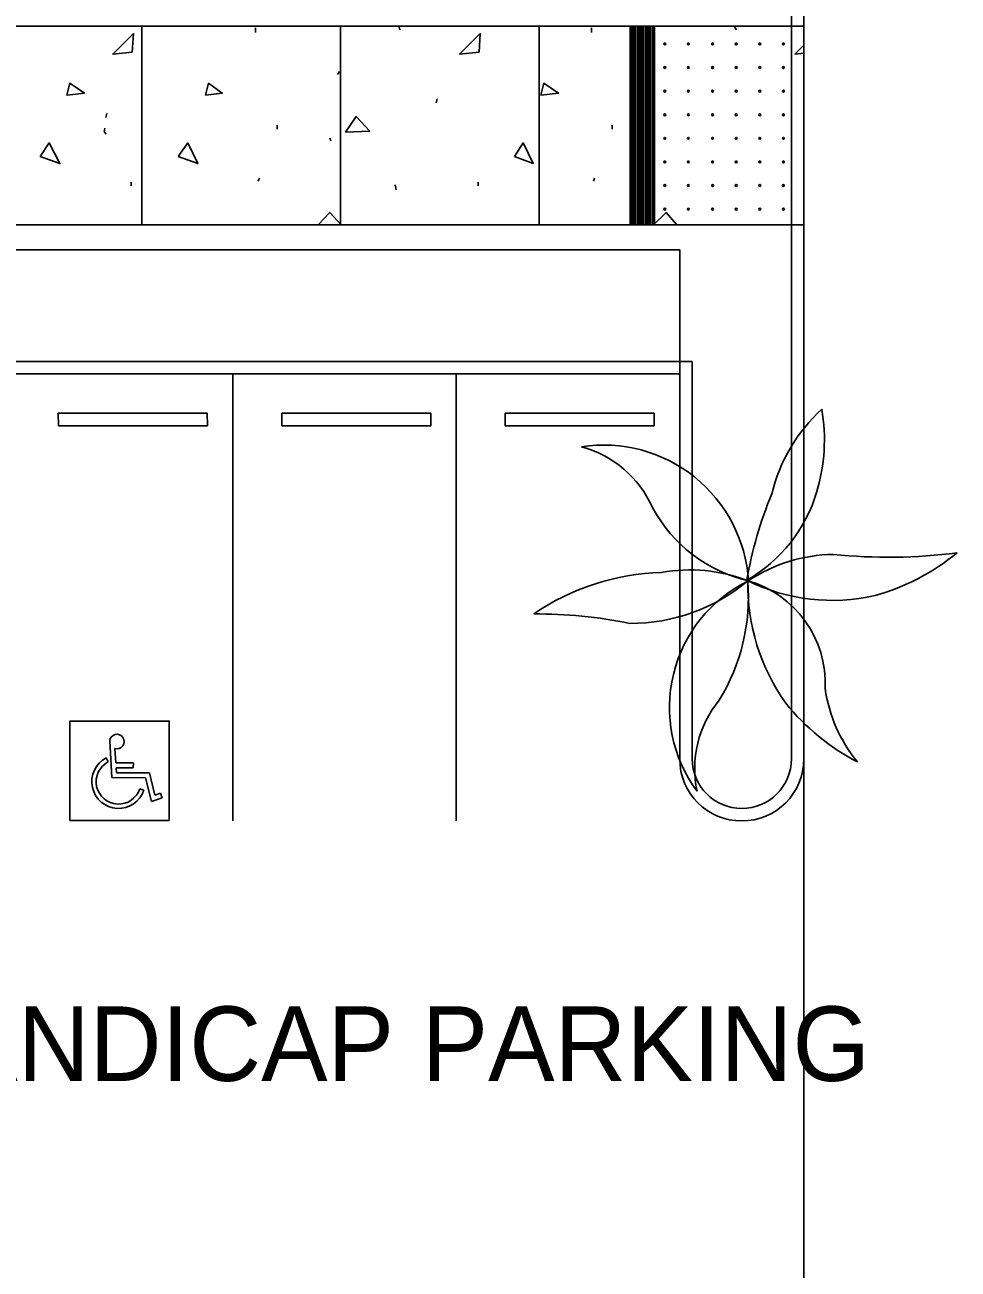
# Model space of a CAD drawing. Extents: x 6712138 to 6712574, y 1869536 to 1870160.
# Drawn here: x 6712529.2 to 6712566.8, y 1869691 to 1869741.1 of the extents above; entities that cross this region are included whole.
import ezdxf

# ---------------------------------------------------------------- set-up
doc = ezdxf.new("R2010")
doc.units = 0
for name, color, linetype in [('A-ANNO-TEXT', 7, 'Continuous'), ('A-FLOR-CASE', 7, 'Continuous'), ('A-FLOR-HRAL', 7, 'Continuous'), ('A-FLOR-PATT', 7, 'Continuous'), ('C-Boun-Imaginary', 7, 'Continuous'), ('C-PRKG-CONC', 7, 'Continuous'), ('E-EQPM', 7, 'Continuous'), ('L-Palm', 7, 'Continuous'), ('L-PLNT-PALM', 7, 'Continuous'), ('L-SITE-PAVE', 7, 'Continuous')]:
    doc.layers.add(name, color=color, linetype=linetype)

# ---------------------------------------------------------------- blocks, each defined once
blk = doc.blocks.new('G-handy2')
for p, q in [((0, 0), (-0.0002239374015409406, 0.0035868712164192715)), ((0.000380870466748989, 0.0014482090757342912), (0.0002942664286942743, 0.002835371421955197)), ((-0.000552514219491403, 0.001912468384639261), (-0.0003555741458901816, 0.001537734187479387)), ((0.0020983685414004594, 0.0014486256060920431), (0.000380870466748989, 0.0014482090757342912)), ((0.0020984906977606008, 0.0009449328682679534), (0.0020983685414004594, 0.0014486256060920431)), ((0, 0), (0.0033054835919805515, 8.016511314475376e-07)), ((0.0004123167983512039, 0.0009445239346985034), (0.0020984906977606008, 0.0009449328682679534)), ((0.0004419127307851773, 0.0004704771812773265), (0.0004123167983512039, 0.0009445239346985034)), ((0.0004419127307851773, 0.0004704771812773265), (0.0036734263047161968, 0.00047126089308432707)), ((0.0033054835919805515, 8.016511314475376e-07), (0.0038831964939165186, -0.0023286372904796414)), ((0.0036734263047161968, 0.00047126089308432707), (0.004214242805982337, -0.0017094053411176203)), ((0.002744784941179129, -0.0010810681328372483), (0.00314717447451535, -0.0012125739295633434)), ((0.0038831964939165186, -0.0023286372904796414), (0.004932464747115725, -0.0019506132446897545)), ((0.004214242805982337, -0.0017094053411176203), (0.004773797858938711, -0.0015078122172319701)), ((0.004773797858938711, -0.0015078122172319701), (0.004932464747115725, -0.0019506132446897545))]:
    blk.add_line(p, q)
for centre, radius, start, end in [((0.000485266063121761, 0.0035214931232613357), 0.0007122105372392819, 254.44408755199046, 174.7330607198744), ((0.0006632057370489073, -0.0004007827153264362), 0.0026132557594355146, 117.72399317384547, 341.90197805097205), ((0.0006632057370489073, -0.0004007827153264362), 0.002189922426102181, 117.72399317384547, 341.90197805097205)]:
    blk.add_arc(centre, radius, start, end)
blk = doc.blocks.new('PALM_1')
at = {"layer": 'L-Palm'}
for centre, radius, start, end in [((0.3858816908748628, 0.09873325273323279), 0.34221757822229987, 132.68010435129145, 166.81114852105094), ((-0.21143464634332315, 0.28561485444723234), 0.37101049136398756, 343.75222667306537, 10.043027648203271), ((-0.2899606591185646, -0.022563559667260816), 0.2967686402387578, 4.087292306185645, 99.25548110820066), ((-0.39302858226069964, 0.05608944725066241), 0.22128274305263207, 24.255185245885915, 75.5182453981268), ((-0.15274376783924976, 0.2676552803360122), 0.3096398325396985, 300.1112673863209, 343.904156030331), ((0.8252462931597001, -0.13741070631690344), 0.8340140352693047, 157.86674178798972, 170.53070431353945), ((0.0708143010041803, 0.2901008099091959), 0.2986187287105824, 208.6353551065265, 257.4748050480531), ((0.18676748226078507, -0.2704983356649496), 0.3242322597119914, 91.33821581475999, 124.03846979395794), ((0.28486508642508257, 1.1557831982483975), 1.1071917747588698, 264.52338670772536, 277.67922172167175), ((0.135809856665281, 0.4172046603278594), 0.46568911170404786, 286.170218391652, 309.6262415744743), ((-0.15629416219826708, -0.4705840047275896), 0.4851124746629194, 91.86864634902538, 124.78454736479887), ((-0.11167863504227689, -0.3018879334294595), 0.3218826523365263, 68.83970088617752, 100.82163772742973), ((-0.23642088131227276, 0.2824980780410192), 0.3725896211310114, 270.04016442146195, 310.28947437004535), ((0.13458695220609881, -0.25968764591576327), 0.2885535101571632, 116.79246646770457, 216.83420096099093), ((-0.3945711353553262, -0.03767575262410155), 0.40067112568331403, 328.61828925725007, 5.092334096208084), ((0.4257094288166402, -0.005139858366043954), 0.4211708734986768, 179.48335083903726, 215.7869865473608), ((-0.05353262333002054, -0.21154565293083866), 0.21808204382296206, 357.61340264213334, 74.5522287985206), ((0.17555123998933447, 0.35411295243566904), 0.3945638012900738, 244.43426343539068, 283.17767034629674), ((-0.4218083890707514, -1.038616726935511), 0.9665224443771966, 78.92586106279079, 90.6662430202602), ((0.46385654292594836, -0.1764782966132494), 0.3027327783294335, 188.38557403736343, 219.82450952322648), ((0.11976543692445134, -0.3851968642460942), 0.22128274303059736, 141.1268158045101, 192.38987595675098), ((0.4441476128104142, 0.043868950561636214), 0.46568911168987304, 219.35404246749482, 242.81006565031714)]:
    blk.add_arc(centre, radius, start, end, dxfattribs=at)

msp = doc.modelspace()

# ---------------------------------------------------------------- linework, layer by layer
at = {"layer": 'A-FLOR-CASE'}
for points in [[(6712495.057149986, 1869765.1727473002), (6712479.05714529, 1869765.1727473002), (6712479.057145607, 1869725.672748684), (6712495.07073085, 1869725.6727812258), (6712495.07073085, 1869733.0729383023), (6712560.557711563, 1869733.0729017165), (6712560.557711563, 1869741.0728234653), (6712495.07073085, 1869741.0729369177)], [(6712528.557761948, 1869732.0729195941), (6712555.557759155, 1869732.0729195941), (6712555.557759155, 1869727.0727714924), (6712528.557761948, 1869727.0727714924)]]:
    msp.add_lwpolyline(points, close=True, dxfattribs=at)
at = {"layer": 'A-FLOR-HRAL'}
msp.add_lwpolyline([(6712560.557231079, 1869857.3207030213), (6712560.557231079, 1869624.5407730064)], dxfattribs=at)
at = {"layer": 'A-FLOR-PATT'}
for p, q in [((6712544.289380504, 1869740.9306967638), (6712544.259380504, 1869741.0506967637)), ((6712557.839380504, 1869740.9306967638), (6712557.759380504, 1869741.0506967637)), ((6712538.4693805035, 1869740.8106967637), (6712538.4693805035, 1869741.0106967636)), ((6712552.009380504, 1869740.8106967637), (6712552.009380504, 1869741.0106967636)), ((6712541.769380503, 1869739.1206967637), (6712541.849380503, 1869739.2406967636)), ((6712545.749380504, 1869737.9806967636), (6712545.789380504, 1869738.1406967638)), ((6712532.439380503, 1869737.3906967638), (6712532.479380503, 1869737.5506967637)), ((6712539.339380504, 1869736.9206967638), (6712539.339380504, 1869737.0806967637)), ((6712552.839380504, 1869736.9206967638), (6712552.839380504, 1869737.0806967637)), ((6712532.369380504, 1869736.8006967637), (6712532.399380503, 1869736.9606967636)), ((6712532.399380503, 1869736.8006967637), (6712532.439380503, 1869736.7206967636)), ((6712541.499380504, 1869736.4506967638), (6712541.459380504, 1869736.5606967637)), ((6712533.459380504, 1869734.6406967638), (6712533.459380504, 1869734.7906967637)), ((6712538.579380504, 1869734.8306967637), (6712538.629380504, 1869734.9506967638)), ((6712544.139380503, 1869734.4806967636), (6712544.099380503, 1869734.6806967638)), ((6712547.439380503, 1869734.6406967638), (6712547.439380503, 1869734.7906967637)), ((6712552.089380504, 1869734.8306967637), (6712552.129380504, 1869734.9506967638))]:
    msp.add_line(p, q, dxfattribs=at)
for points in [[(6712533.499380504, 1869740.0306967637), (6712533.549380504, 1869740.7706967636), (6712532.7193805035, 1869739.9506967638)], [(6712547.479380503, 1869740.0306967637), (6712547.519380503, 1869740.7706967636), (6712546.689380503, 1869739.9506967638)], [(6712530.869380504, 1869738.2906967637), (6712531.579380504, 1869738.3806967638), (6712530.989380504, 1869738.7706967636)], [(6712536.459380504, 1869738.2906967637), (6712537.129380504, 1869738.3806967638), (6712536.579380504, 1869738.7706967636)], [(6712549.959380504, 1869738.2906967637), (6712550.6793805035, 1869738.3806967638), (6712550.079380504, 1869738.7706967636)], [(6712542.089380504, 1869736.8006967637), (6712542.519380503, 1869737.4306967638), (6712543.069380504, 1869736.8406967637)], [(6712529.799380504, 1869735.8206967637), (6712530.589380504, 1869735.5406967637), (6712530.159380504, 1869736.3706967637)], [(6712535.349380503, 1869735.8206967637), (6712536.139380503, 1869735.5406967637), (6712535.749380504, 1869736.3706967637)], [(6712548.899380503, 1869735.8206967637), (6712549.649380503, 1869735.5406967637), (6712549.249380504, 1869736.3706967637)]]:
    msp.add_lwpolyline(points, close=True, dxfattribs=at)
for points in [[(6712560.557711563, 1869740.3090278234), (6712560.199380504, 1869739.9506967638), (6712560.557711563, 1869739.9869834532)], [(6712540.997798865, 1869733.0729126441), (6712541.459380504, 1869733.5706967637), (6712541.9255597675, 1869733.0729121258)], [(6712554.502538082, 1869733.0729050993), (6712555.009380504, 1869733.5706967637), (6712555.43605952, 1869733.0729045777)]]:
    msp.add_lwpolyline(points, dxfattribs=at)
at = {"layer": 'C-Boun-Imaginary'}
for points in [[(6712560.557711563, 1869862.1070740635), (6712560.557711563, 1869624.540443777)], [(6712560.557711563, 1869859.5000032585), (6712560.557711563, 1869624.540443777)]]:
    msp.add_lwpolyline(points, dxfattribs=at)
at = {"layer": 'C-PRKG-CONC'}
for p, q in [((6712560.057744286, 1869711.572771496), (6712560.057711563, 1869792.5728820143)), ((6712560.557744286, 1869711.5727714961), (6712560.557711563, 1869792.5728820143)), ((6712560.557711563, 1869741.0728234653), (6712495.07073085, 1869741.0729369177)), ((6712560.557711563, 1869733.0729017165), (6712495.07073085, 1869733.0729383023)), ((6712528.55776134, 1869727.5727714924), (6712556.057744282, 1869727.5727714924)), ((6712556.057744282, 1869711.5727714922), (6712556.057744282, 1869727.5727714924)), ((6712528.55776134, 1869727.0727714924), (6712555.557759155, 1869727.0727714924)), ((6712537.557759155, 1869709.0727714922), (6712537.557759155, 1869727.0727714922)), ((6712546.557759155, 1869709.0727714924), (6712546.557759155, 1869727.0727714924)), ((6712555.557744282, 1869711.5727714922), (6712555.557744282, 1869727.0727714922)), ((6712536.525504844, 1869725.4867916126), (6712530.525379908, 1869725.4867651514)), ((6712530.525379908, 1869725.4867651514), (6712530.528608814, 1869724.9867651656)), ((6712530.528608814, 1869724.9867651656), (6712536.528733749, 1869724.9867916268)), ((6712536.528733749, 1869724.9867916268), (6712536.525504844, 1869725.486791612)), ((6712545.525502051, 1869725.4867916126), (6712539.525377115, 1869725.4867651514)), ((6712539.525377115, 1869725.4867651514), (6712539.528606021, 1869724.9867651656)), ((6712539.528606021, 1869724.9867651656), (6712545.528730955, 1869724.9867916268)), ((6712545.528730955, 1869724.9867916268), (6712545.525502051, 1869725.486791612)), ((6712554.525502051, 1869725.4867916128), (6712548.525377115, 1869725.4867651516)), ((6712548.525377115, 1869725.4867651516), (6712548.528606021, 1869724.9867651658)), ((6712548.528606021, 1869724.9867651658), (6712554.528730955, 1869724.986791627)), ((6712554.528730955, 1869724.986791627), (6712554.525502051, 1869725.4867916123))]:
    msp.add_line(p, q, dxfattribs=at)
msp.add_lwpolyline([(6712534.993337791, 1869709.0960788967), (6712530.99333779, 1869709.0960788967), (6712530.99333779, 1869713.0960788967), (6712534.99333779, 1869713.0960788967)], close=True, dxfattribs=at)
for radius, start, end in [(2.5, 180, 270), (2, 180, 270), (2.5, 270, 0), (2, 270, 0)]:
    msp.add_arc((6712558.057744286, 1869711.5727714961), radius, start, end, dxfattribs=at)
at = {"layer": 'E-EQPM'}
for centre in [(6712554.9543900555, 1869740.3557246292), (6712555.904390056, 1869740.3557246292), (6712556.883390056, 1869740.3557246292), (6712557.833390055, 1869740.3557246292), (6712558.783390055, 1869740.3557246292), (6712559.733390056, 1869740.3557246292), (6712554.9543900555, 1869739.4057246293), (6712555.904390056, 1869739.4057246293), (6712556.883390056, 1869739.4057246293), (6712557.833390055, 1869739.4057246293), (6712558.783390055, 1869739.4057246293), (6712559.733390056, 1869739.4057246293), (6712554.9543900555, 1869738.4557246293), (6712555.904390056, 1869738.4557246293), (6712556.883390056, 1869738.4557246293), (6712557.833390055, 1869738.4557246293), (6712558.783390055, 1869738.4557246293), (6712559.733390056, 1869738.4557246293), (6712554.9543900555, 1869737.5057246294), (6712555.904390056, 1869737.5057246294), (6712556.883390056, 1869737.5057246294), (6712557.833390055, 1869737.5057246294), (6712558.783390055, 1869737.5057246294), (6712559.733390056, 1869737.5057246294), (6712554.9543900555, 1869736.5557246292), (6712555.904390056, 1869736.5557246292), (6712556.883390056, 1869736.5557246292), (6712557.833390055, 1869736.5557246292), (6712558.783390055, 1869736.5557246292), (6712559.733390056, 1869736.5557246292), (6712554.9543900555, 1869735.6057246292), (6712555.904390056, 1869735.6057246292), (6712556.883390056, 1869735.6057246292), (6712557.833390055, 1869735.6057246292), (6712558.783390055, 1869735.6057246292), (6712559.733390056, 1869735.6057246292), (6712554.9543900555, 1869734.6557246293), (6712555.904390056, 1869734.6557246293), (6712556.883390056, 1869734.6557246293), (6712557.833390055, 1869734.6557246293), (6712558.783390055, 1869734.6557246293), (6712559.733390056, 1869734.6557246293), (6712554.9543900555, 1869733.7057246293), (6712555.904390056, 1869733.7057246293), (6712556.883390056, 1869733.7057246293), (6712557.833390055, 1869733.7057246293), (6712558.783390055, 1869733.7057246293), (6712559.733390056, 1869733.7057246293)]:
    msp.add_circle(centre, 0.0375, dxfattribs=at)
at = {"layer": 'L-SITE-PAVE'}
for p, q in [((6712533.891044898, 1869741.0732739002), (6712533.891044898, 1869733.0732739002)), ((6712541.891044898, 1869741.0732739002), (6712541.891044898, 1869733.0732739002)), ((6712549.891044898, 1869741.0734413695), (6712549.891044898, 1869733.0734413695)), ((6712553.557707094, 1869733.0728234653), (6712553.557707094, 1869741.0728234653)), ((6712554.557711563, 1869741.0728234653), (6712553.557707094, 1869741.0728234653)), ((6712553.627707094, 1869733.0728234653), (6712553.627707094, 1869741.0728234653)), ((6712553.697707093, 1869733.0728234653), (6712553.697707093, 1869741.0728234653)), ((6712553.767707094, 1869733.0728234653), (6712553.767707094, 1869741.0728234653)), ((6712553.837707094, 1869733.0728234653), (6712553.837707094, 1869741.0728234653)), ((6712553.907707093, 1869733.0728234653), (6712553.907707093, 1869741.0728234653)), ((6712553.977707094, 1869733.0728234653), (6712553.977707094, 1869741.0728234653)), ((6712554.047707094, 1869733.0728234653), (6712554.047707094, 1869741.0728234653)), ((6712554.117707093, 1869733.0728234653), (6712554.117707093, 1869741.0728234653)), ((6712554.187707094, 1869733.0728234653), (6712554.187707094, 1869741.0728234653)), ((6712554.257707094, 1869733.0728234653), (6712554.257707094, 1869741.0728234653)), ((6712554.327707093, 1869733.0728234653), (6712554.327707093, 1869741.0728234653)), ((6712554.3977070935, 1869733.0728234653), (6712554.3977070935, 1869741.0728234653)), ((6712554.467707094, 1869733.0728234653), (6712554.467707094, 1869741.0728234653)), ((6712554.537707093, 1869733.0728234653), (6712554.537707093, 1869741.0728234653)), ((6712554.557707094, 1869733.0728234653), (6712553.557707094, 1869733.0728234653))]:
    msp.add_line(p, q, dxfattribs=at)

# ---------------------------------------------------------------- block references
at = {"layer": 'C-PRKG-CONC', "xscale": 412.3229143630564, "yscale": 412.3229143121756, "rotation": -0.2605055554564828}
msp.add_blockref('G-handy2', (6712532.680065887, 1869710.819154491), dxfattribs=at)
at = {"layer": 'L-PLNT-PALM', "xscale": 19.685039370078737, "yscale": 19.68503937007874, "rotation": -0.36974722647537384}
msp.add_blockref('PALM_1', (6712558.207918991, 1869718.771340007), dxfattribs=at)

# ---------------------------------------------------------------- texts
at = {"layer": 'A-ANNO-TEXT'}
msp.add_text('VISITOR/ HANDICAP PARKING ', height=3, dxfattribs=at).set_placement((6712505.0406200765, 1869698.6050266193))

doc.saveas('drawing.dxf')
